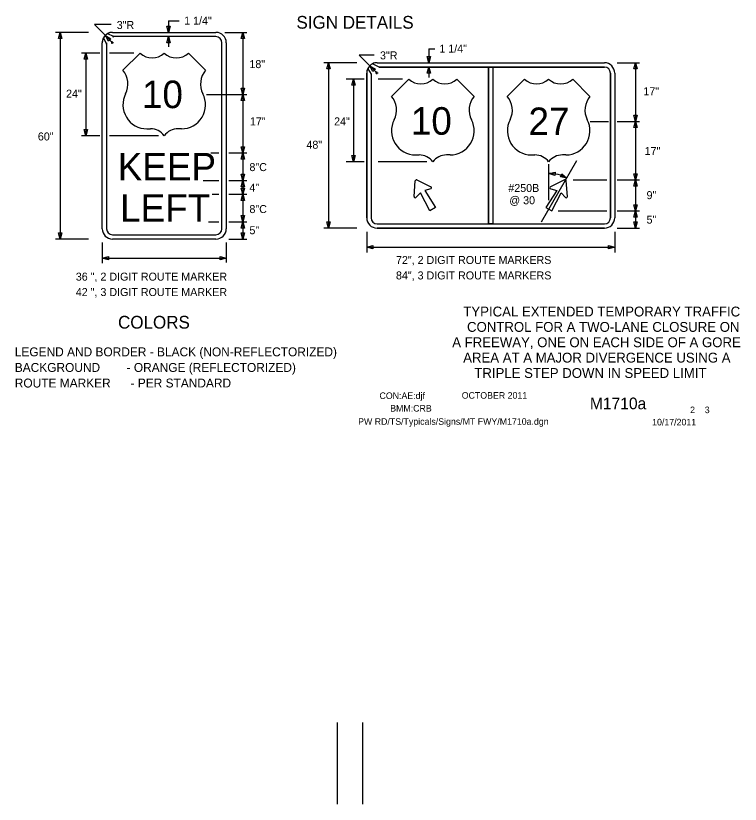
# Model space of a CAD drawing. Extents: x 16630 to 19509, y 5576 to 6998.
# Drawn here: x 17777 to 18460, y 5576 to 6320 of the extents above; entities that cross this region are included whole.
import ezdxf

# ---------------------------------------------------------------- set-up
doc = ezdxf.new("R2010")
doc.units = 0
for name, color, linetype in [('ALI_LEGAL_EX', 7, 'Continuous'), ('BORDER', 7, 'Continuous'), ('BORDER_SIGNAL_WO', 7, 'Continuous'), ('TRAFFIC_SIGNS_PR', 7, 'Continuous'), ('TYPICAL_EX', 7, 'Continuous'), ('TYPICAL_TEXT_DIMEN_PR', 7, 'Continuous')]:
    doc.layers.add(name, color=color, linetype=linetype)

msp = doc.modelspace()

# ---------------------------------------------------------------- linework, layer by layer
at = {"layer": 'ALI_LEGAL_EX'}
for p, q in [((18079.61, 5652.91), (18079.61, 5575.75)), ((18103.61, 5652.91), (18103.61, 5575.75))]:
    msp.add_line(p, q, dxfattribs=at)
at = {"layer": 'TRAFFIC_SIGNS_PR'}
for p, q in [((17860.3, 6300.32), (17859.29, 6298.82)), ((17869.08, 6299.88), (17862.99, 6302.62)), ((17867.88, 6303.94), (17965.38, 6303.94)), ((17858.13, 6118.69), (17858.13, 6294.19)), ((17859.32, 6298.74), (17862.19, 6292.7)), ((17862.19, 6294.19), (17862.19, 6118.69)), ((17965.38, 6299.88), (17867.88, 6299.88)), ((17971.06, 6118.69), (17971.06, 6294.19)), ((17975.13, 6294.19), (17975.13, 6118.69)), ((18119.35, 6271.19), (18113.12, 6274.21)), ((18117.4, 6275.24), (18331.9, 6275.24)), ((18117.4, 6275.24), (18331.9, 6275.24)), ((18119.34, 6271.18), (18222.62, 6271.18)), ((18331.9, 6271.18), (18119.34, 6271.18)), ((18222.62, 6271.18), (18222.62, 6123.31)), ((18226.68, 6271.18), (18226.68, 6123.31)), ((18226.68, 6271.18), (18331.9, 6271.18)), ((18107.65, 6265.49), (18107.65, 6128.99)), ((18107.65, 6128.99), (18107.65, 6265.49)), ((18108.57, 6269.5), (18111.71, 6264.46)), ((18111.71, 6264.44), (18111.71, 6128.99)), ((18111.71, 6264.44), (18111.71, 6128.99)), ((18337.59, 6265.49), (18337.59, 6219.74)), ((18337.59, 6128.99), (18337.59, 6265.49)), ((18341.65, 6265.49), (18341.65, 6128.99)), ((18341.65, 6265.49), (18341.65, 6128.99)), ((18337.59, 6219.74), (18337.59, 6128.99)), ((18152.25, 6149.1), (18153.4, 6163.82)), ((18154.91, 6164.69), (18168.23, 6158.33)), ((18294.38, 6164.69), (18281.07, 6158.33)), ((18297.05, 6149.1), (18295.9, 6163.82)), ((18117.4, 6123.31), (18331.9, 6123.31)), ((18117.4, 6119.24), (18331.9, 6119.24)), ((18331.9, 6119.24), (18117.4, 6119.24)), ((17867.88, 6113), (17965.38, 6113)), ((17965.38, 6108.94), (17867.88, 6108.94))]:
    msp.add_line(p, q, dxfattribs=at)
for points in [[(18119.34, 6271.18), (18119.32, 6271.19)], [(18111.71, 6264.46), (18111.71, 6264.44)], [(18168.07, 6156.36), (18162.34, 6154.78), (18172.56, 6138.61), (18167.16, 6135.49), (18158.27, 6152.43), (18154.04, 6148.26)], [(18281.23, 6156.36), (18286.96, 6154.78), (18276.74, 6138.61), (18282.14, 6135.49), (18291.03, 6152.43), (18295.26, 6148.26)]]:
    msp.add_lwpolyline(points, dxfattribs=at)
msp.add_lwpolyline([(18222.62, 6271.18), (18226.68, 6271.18), (18226.68, 6123.31), (18222.62, 6123.31)], close=True, dxfattribs=at)
for centre, radius, start, end in [((17867.88, 6294.19), 9.75, 90, 180), ((17867.29, 6296.37), 7.6, 85.58319, 124.53531), ((17965.38, 6294.19), 9.75, 0, 90), ((17865.16, 6294.78), 7.06, 145.86811, 184.82317), ((17856.73, 6293.45), 5.51, 352.24294, 7.75653), ((17868.48, 6304.31), 4.47, 262.2432, 277.7568), ((17965.38, 6294.19), 5.69, 0, 90), ((18117.4, 6265.49), 9.75, 90, 180), ((18117.4, 6265.49), 9.75, 90, 180), ((18116.72, 6268.68), 6.6, 84.11162, 123.06374), ((18118.34, 6278.36), 7.24, 277.81035, 278.05403), ((18331.9, 6265.49), 9.75, 0, 90), ((18331.9, 6265.49), 9.75, 0, 90), ((18331.9, 6265.49), 5.69, 0, 89.99421), ((18331.9, 6265.49), 5.69, 0, 90), ((18113.78, 6266.2), 6.17, 147.60925, 186.56283), ((18154.46, 6163.73), 1.06, 64.48226, 175.51774), ((18294.84, 6163.73), 1.06, 4.48226, 115.51774), ((18167.77, 6157.38), 1.06, 285.9885, 64.48226), ((18281.53, 6157.38), 1.06, 115.51774, 254.0115), ((18153.31, 6149.02), 1.06, 175.51775, 314.01151), ((18295.99, 6149.02), 1.06, 225.98849, 4.48225), ((18117.4, 6128.99), 9.75, 180, 270), ((18117.4, 6128.99), 9.75, 180, 270), ((18117.4, 6128.99), 5.69, 180, 270), ((18117.4, 6128.99), 5.69, 180, 270), ((18331.9, 6128.99), 9.75, 270, 0), ((18331.9, 6128.99), 5.69, 270, 0), ((18331.9, 6128.99), 9.75, 270, 0), ((18331.9, 6128.99), 5.69, 270, 0), ((17867.88, 6118.69), 9.75, 180, 270), ((17867.88, 6118.69), 5.69, 180, 270), ((17965.38, 6118.69), 5.69, 270, 0), ((17965.38, 6118.69), 9.75, 270, 0)]:
    msp.add_arc(centre, radius, start, end, dxfattribs=at)
at = {"layer": 'TYPICAL_EX'}
for p, q in [((17877.63, 6268.19), (17893.88, 6284.44)), ((17955.63, 6268.19), (17939.38, 6284.44)), ((18131.01, 6243.58), (18147.26, 6259.83)), ((18209.01, 6243.58), (18192.76, 6259.83)), ((18240.29, 6243.58), (18256.54, 6259.83)), ((18318.29, 6243.58), (18302.04, 6259.83)), ((17900.35, 6212.9), (17903.6, 6212.9)), ((17932.9, 6212.9), (17929.65, 6212.9)), ((18153.74, 6188.29), (18156.99, 6188.29)), ((18186.28, 6188.29), (18183.03, 6188.29)), ((18263.01, 6188.29), (18266.26, 6188.29)), ((18295.56, 6188.29), (18292.31, 6188.29))]:
    msp.add_line(p, q, dxfattribs=at)
for centre, radius, start, end in [((17905.25, 6296.28), 16.42, 226.14041, 313.85958), ((17928, 6296.28), 16.42, 226.14042, 313.85959), ((17862.23, 6255.18), 20.16, 333.09768, 40.19361), ((17971.03, 6255.18), 20.16, 139.80639, 206.90233), ((18158.64, 6271.67), 16.42, 226.14041, 313.85958), ((18181.39, 6271.67), 16.42, 226.14042, 313.85959), ((18267.91, 6271.67), 16.42, 226.14041, 313.85958), ((18290.66, 6271.67), 16.42, 226.14042, 313.85959), ((17900.4, 6235.63), 22.73, 152.6698, 269.90132), ((17932.86, 6235.63), 22.73, 270.09868, 27.3302), ((18115.61, 6230.57), 20.16, 333.09768, 40.19361), ((18224.41, 6230.57), 20.16, 139.80639, 206.90233), ((18224.89, 6230.57), 20.16, 333.09768, 40.19361), ((18333.69, 6230.57), 20.16, 139.80639, 206.90233), ((18153.78, 6211.02), 22.73, 152.6698, 269.90132), ((18186.24, 6211.02), 22.73, 270.09868, 27.3302), ((18263.06, 6211.02), 22.73, 152.6698, 269.90132), ((18295.52, 6211.02), 22.73, 270.09868, 27.3302), ((17903.65, 6196.62), 16.28, 37.1038, 90.13853), ((17929.61, 6196.62), 16.28, 89.86147, 142.8962), ((18157.03, 6172.01), 16.28, 37.1038, 90.13853), ((18182.99, 6172.01), 16.28, 89.86147, 142.8962), ((18266.31, 6172.01), 16.28, 37.1038, 90.13853), ((18292.27, 6172.01), 16.28, 89.86147, 142.8962)]:
    msp.add_arc(centre, radius, start, end, dxfattribs=at)
at = {"layer": 'TYPICAL_TEXT_DIMEN_PR'}
for p, q in [((17866.5, 6311.23), (17850.84, 6311.23)), ((17850.84, 6311.23), (17861.08, 6300.99)), ((17920.6, 6303.94), (17919.03, 6309.8)), ((17919.03, 6309.8), (17920.6, 6309.8)), ((17920.6, 6314.7), (17920.6, 6303.94)), ((17920.6, 6314.7), (17930.71, 6314.7)), ((17920.6, 6309.8), (17922.17, 6309.8)), ((17922.17, 6309.8), (17920.6, 6303.94)), ((17845.3, 6303.94), (17814, 6303.94)), ((17816.77, 6298.08), (17818.34, 6303.94)), ((17818.34, 6303.94), (17818.34, 6108.94)), ((17818.34, 6303.94), (17819.91, 6298.08)), ((17861.08, 6300.99), (17867.64, 6294.43)), ((17864.11, 6295.73), (17861.08, 6300.99)), ((17861.08, 6300.99), (17866.33, 6297.95)), ((17973.67, 6303.94), (17994.63, 6303.94)), ((17989.16, 6298.08), (17990.73, 6303.94)), ((17990.73, 6303.94), (17990.73, 6245.44)), ((17990.73, 6303.94), (17992.3, 6298.08)), ((17818.34, 6298.08), (17816.77, 6298.08)), ((17819.91, 6298.08), (17818.34, 6298.08)), ((17865.22, 6296.84), (17864.11, 6295.73)), ((17866.33, 6297.95), (17865.22, 6296.84)), ((17866.43, 6294.43), (17868.85, 6294.43)), ((17867.64, 6293.22), (17867.64, 6295.64)), ((17919.08, 6294.02), (17920.65, 6299.88)), ((17920.65, 6294.02), (17919.08, 6294.02)), ((17920.65, 6299.88), (17920.65, 6290.13)), ((17920.65, 6299.88), (17922.22, 6294.02)), ((17922.22, 6294.02), (17920.65, 6294.02)), ((17990.73, 6298.08), (17989.16, 6298.08)), ((17992.3, 6298.08), (17990.73, 6298.08)), ((18166.26, 6288.4), (18166.26, 6275.24)), ((18166.26, 6288.4), (18171.78, 6288.4)), ((17855.76, 6284.44), (17838.63, 6284.44)), ((17840.95, 6278.58), (17842.52, 6284.44)), ((17842.52, 6278.58), (17840.95, 6278.58)), ((17842.52, 6284.44), (17842.52, 6206.44)), ((17842.52, 6284.44), (17844.1, 6278.58)), ((17844.1, 6278.58), (17842.52, 6278.58)), ((17887.99, 6284.44), (17865.12, 6284.44)), ((18114.54, 6282.53), (18100.36, 6282.53)), ((18100.36, 6282.53), (18110.51, 6272.38)), ((18166.26, 6275.24), (18164.69, 6281.11)), ((18164.69, 6281.11), (18166.26, 6281.11)), ((18166.26, 6281.11), (18167.83, 6281.11)), ((18167.83, 6281.11), (18166.26, 6275.24)), ((18098.42, 6275.24), (18067.12, 6275.24)), ((18069.89, 6269.38), (18071.46, 6275.24)), ((18071.46, 6275.24), (18071.46, 6119.24)), ((18071.46, 6275.24), (18073.03, 6269.38)), ((18110.51, 6272.38), (18117.16, 6265.73)), ((18113.55, 6267.12), (18110.51, 6272.38)), ((18110.51, 6272.38), (18115.77, 6269.35)), ((18164.74, 6265.32), (18166.31, 6271.18)), ((18164.74, 6265.32), (18166.31, 6271.18)), ((18166.31, 6271.18), (18166.31, 6261.43)), ((18166.31, 6271.18), (18167.88, 6265.32)), ((18166.31, 6271.18), (18167.88, 6265.32)), ((18344.02, 6275.24), (18364.98, 6275.24)), ((18359.51, 6269.38), (18361.08, 6275.24)), ((18361.08, 6275.24), (18361.08, 6219.99)), ((18361.08, 6275.24), (18362.66, 6269.38)), ((18071.46, 6269.38), (18069.89, 6269.38)), ((18073.03, 6269.38), (18071.46, 6269.38)), ((18114.66, 6268.23), (18113.55, 6267.12)), ((18115.77, 6269.35), (18114.66, 6268.23)), ((18115.95, 6265.73), (18118.37, 6265.73)), ((18117.16, 6264.53), (18117.16, 6266.94)), ((18166.31, 6265.32), (18164.74, 6265.32)), ((18166.31, 6265.32), (18164.74, 6265.32)), ((18167.88, 6265.32), (18166.31, 6265.32)), ((18167.88, 6265.32), (18166.31, 6265.32)), ((18361.08, 6269.38), (18359.51, 6269.38)), ((18362.66, 6269.38), (18361.08, 6269.38)), ((18105.28, 6259.83), (18088.15, 6259.83)), ((18093.45, 6253.97), (18095.02, 6259.83)), ((18095.02, 6259.83), (18095.02, 6181.83)), ((18095.02, 6259.83), (18096.59, 6253.97)), ((18141.38, 6259.83), (18118.5, 6259.83)), ((17990.73, 6245.44), (17989.16, 6251.3)), ((17989.16, 6251.3), (17990.73, 6251.3)), ((17990.73, 6251.3), (17992.3, 6251.3)), ((17992.3, 6251.3), (17990.73, 6245.44)), ((18095.02, 6253.97), (18093.45, 6253.97)), ((18096.59, 6253.97), (18095.02, 6253.97)), ((17956.52, 6245.44), (17994.63, 6245.44)), ((17989.16, 6239.58), (17990.73, 6245.44)), ((17990.73, 6245.44), (17990.73, 6190.19)), ((17990.73, 6245.44), (17992.3, 6239.58)), ((17990.73, 6239.58), (17989.16, 6239.58)), ((17992.3, 6239.58), (17990.73, 6239.58)), ((18318.46, 6219.99), (18335.62, 6219.99)), ((18344.02, 6219.99), (18364.98, 6219.99)), ((18361.08, 6219.99), (18359.51, 6225.86)), ((18359.51, 6225.86), (18361.08, 6225.86)), ((18359.51, 6214.13), (18361.08, 6219.99)), ((18361.08, 6225.86), (18362.66, 6225.86)), ((18362.66, 6225.86), (18361.08, 6219.99)), ((18361.08, 6219.99), (18361.08, 6164.74)), ((18361.08, 6219.99), (18362.66, 6214.13)), ((17842.52, 6206.44), (17840.95, 6212.3)), ((17840.95, 6212.3), (17842.52, 6212.3)), ((17842.52, 6212.3), (17844.1, 6212.3)), ((17844.1, 6212.3), (17842.52, 6206.44)), ((18361.08, 6214.13), (18359.51, 6214.13)), ((18362.66, 6214.13), (18361.08, 6214.13)), ((17855.76, 6206.44), (17838.63, 6206.44)), ((17911.12, 6206.44), (17865.12, 6206.44)), ((17960.46, 6190.19), (17968.14, 6190.19)), ((17977.5, 6190.19), (17994.63, 6190.19)), ((17990.73, 6190.19), (17989.16, 6196.05)), ((17989.16, 6196.05), (17990.73, 6196.05)), ((17989.16, 6184.33), (17990.73, 6190.19)), ((17990.73, 6196.05), (17992.3, 6196.05)), ((17992.3, 6196.05), (17990.73, 6190.19)), ((17990.73, 6190.19), (17990.73, 6164.19)), ((17990.73, 6190.19), (17992.3, 6184.33)), ((17990.73, 6184.33), (17989.16, 6184.33)), ((17992.3, 6184.33), (17990.73, 6184.33)), ((18105.28, 6181.83), (18088.15, 6181.83)), ((18095.02, 6181.83), (18093.45, 6187.69)), ((18093.45, 6187.69), (18095.02, 6187.69)), ((18095.02, 6187.69), (18096.59, 6187.69)), ((18096.59, 6187.69), (18095.02, 6181.83)), ((18164.5, 6181.83), (18118.5, 6181.83)), ((18272.68, 6125.34), (18305.92, 6182.93)), ((18279.44, 6145.5), (18279.44, 6179.49)), ((17990.73, 6164.19), (17989.16, 6170.05)), ((17989.16, 6170.05), (17990.73, 6170.05)), ((17990.73, 6170.05), (17992.3, 6170.05)), ((17992.3, 6170.05), (17990.73, 6164.19)), ((18279.47, 6170.94), (18285.46, 6171.9)), ((18285.14, 6168.77), (18279.47, 6170.94)), ((18285.3, 6170.33), (18285.14, 6168.77)), ((18285.46, 6171.9), (18285.3, 6170.33)), ((18290.45, 6167.61), (18291.14, 6169.03)), ((18296.42, 6166.48), (18290.45, 6167.61)), ((18291.14, 6169.03), (18291.82, 6170.44)), ((18291.82, 6170.44), (18296.42, 6166.48)), ((18361.08, 6164.74), (18359.51, 6170.61)), ((18359.51, 6170.61), (18361.08, 6170.61)), ((18361.08, 6170.61), (18362.66, 6170.61)), ((18362.66, 6170.61), (18361.08, 6164.74)), ((17953.44, 6164.19), (17968.14, 6164.19)), ((17977.5, 6164.19), (17994.63, 6164.19)), ((17989.16, 6158.33), (17990.73, 6164.19)), ((17990.73, 6164.19), (17990.73, 6151.19)), ((17990.73, 6164.19), (17992.3, 6158.33)), ((18302.39, 6164.74), (18334.26, 6164.74)), ((18344.02, 6164.74), (18364.98, 6164.74)), ((18359.51, 6158.88), (18361.08, 6164.74)), ((18361.08, 6164.74), (18361.08, 6135.49)), ((18361.08, 6164.74), (18362.66, 6158.88)), ((17990.73, 6158.33), (17989.16, 6158.33)), ((17990.73, 6151.19), (17989.16, 6157.05)), ((17989.16, 6157.05), (17990.73, 6157.05)), ((17992.3, 6158.33), (17990.73, 6158.33)), ((17990.73, 6157.05), (17992.3, 6157.05)), ((17992.3, 6157.05), (17990.73, 6151.19)), ((18361.08, 6158.88), (18359.51, 6158.88)), ((18362.66, 6158.88), (18361.08, 6158.88)), ((17961.79, 6151.19), (17968.14, 6151.19)), ((17977.5, 6151.19), (17994.63, 6151.19)), ((17989.16, 6145.33), (17990.73, 6151.19)), ((17990.73, 6145.33), (17989.16, 6145.33)), ((17990.73, 6151.19), (17990.73, 6125.19)), ((17990.73, 6151.19), (17992.3, 6145.33)), ((17992.3, 6145.33), (17990.73, 6145.33)), ((18361.08, 6135.49), (18359.51, 6141.36)), ((18359.51, 6141.36), (18361.08, 6141.36)), ((18361.08, 6141.36), (18362.66, 6141.36)), ((18362.66, 6141.36), (18361.08, 6135.49)), ((17990.73, 6125.19), (17989.16, 6131.05)), ((17989.16, 6131.05), (17990.73, 6131.05)), ((17990.73, 6131.05), (17992.3, 6131.05)), ((17992.3, 6131.05), (17990.73, 6125.19)), ((18288.26, 6135.49), (18334.26, 6135.49)), ((18344.02, 6135.49), (18364.98, 6135.49)), ((18359.51, 6129.63), (18361.08, 6135.49)), ((18361.08, 6129.63), (18359.51, 6129.63)), ((18361.08, 6135.49), (18361.08, 6119.24)), ((18361.08, 6135.49), (18362.66, 6129.63)), ((18362.66, 6129.63), (18361.08, 6129.63)), ((17958.29, 6125.19), (17968.14, 6125.19)), ((17977.5, 6125.19), (17994.63, 6125.19)), ((17989.16, 6119.33), (17990.73, 6125.19)), ((17990.73, 6125.19), (17990.73, 6108.94)), ((17990.73, 6125.19), (17992.3, 6119.33)), ((18071.46, 6119.24), (18069.89, 6125.11)), ((18069.89, 6125.11), (18071.46, 6125.11)), ((18071.46, 6125.11), (18073.03, 6125.11)), ((18073.03, 6125.11), (18071.46, 6119.24)), ((18361.08, 6119.24), (18359.51, 6125.11)), ((18359.51, 6125.11), (18361.08, 6125.11)), ((18361.08, 6125.11), (18362.66, 6125.11)), ((18362.66, 6125.11), (18361.08, 6119.24)), ((17818.34, 6108.94), (17816.77, 6114.8)), ((17816.77, 6114.8), (17818.34, 6114.8)), ((17818.34, 6114.8), (17819.91, 6114.8)), ((17819.91, 6114.8), (17818.34, 6108.94)), ((17990.73, 6119.33), (17989.16, 6119.33)), ((17990.73, 6108.94), (17989.16, 6114.8)), ((17989.16, 6114.8), (17990.73, 6114.8)), ((17992.3, 6119.33), (17990.73, 6119.33)), ((17990.73, 6114.8), (17992.3, 6114.8)), ((17992.3, 6114.8), (17990.73, 6108.94)), ((18098.42, 6119.24), (18067.12, 6119.24)), ((18107.65, 6115.9), (18107.65, 6096.34)), ((18341.65, 6115.9), (18341.65, 6096.34)), ((18344.02, 6119.24), (18361.15, 6119.24)), ((18344.02, 6119.24), (18364.98, 6119.24)), ((18344.02, 6119.24), (18361.15, 6119.24)), ((17845.3, 6108.94), (17814, 6108.94)), ((17977.5, 6108.94), (17994.63, 6108.94)), ((17858.13, 6105.6), (17858.13, 6086.24)), ((17975.13, 6105.6), (17975.13, 6086.7)), ((18107.65, 6101.27), (18113.51, 6102.84)), ((18107.65, 6101.27), (18341.65, 6101.27)), ((18113.51, 6099.7), (18107.65, 6101.27)), ((18113.51, 6102.84), (18113.51, 6101.27)), ((18113.51, 6101.27), (18113.51, 6099.7)), ((18335.79, 6101.27), (18335.79, 6102.84)), ((18335.79, 6102.84), (18341.65, 6101.27)), ((18341.65, 6101.27), (18335.79, 6099.7)), ((18335.79, 6099.7), (18335.79, 6101.27)), ((17858.13, 6090.97), (17863.99, 6092.54)), ((17863.99, 6092.54), (17863.99, 6090.97)), ((17969.27, 6090.97), (17969.27, 6092.54)), ((17969.27, 6092.54), (17975.13, 6090.97)), ((17858.13, 6090.97), (17975.13, 6090.97)), ((17863.99, 6089.4), (17858.13, 6090.97)), ((17863.99, 6090.97), (17863.99, 6089.4)), ((17975.13, 6090.97), (17969.27, 6089.4)), ((17969.27, 6089.4), (17969.27, 6090.97))]:
    msp.add_line(p, q, dxfattribs=at)
msp.add_arc((18279.63, 6136.5), 34.39, 60.74521, 90.32117, dxfattribs=at)

# ---------------------------------------------------------------- texts
at = {"layer": 'BORDER'}
for s, p in [('TYPICAL EXTENDED TEMPORARY TRAFFIC', (18198.79, 6035.9)), ('CONTROL FOR A TWO-LANE CLOSURE ON', (18202.28, 6021.41)), ('A FREEWAY, ONE ON EACH SIDE OF A GORE', (18188.3, 6006.92)), ('AREA AT A MAJOR DIVERGENCE USING A', (18198.66, 5992.42)), ('TRIPLE STEP DOWN IN SPEED LIMIT', (18209.16, 5977.93))]:
    msp.add_text(s, height=9.3, dxfattribs=at).set_placement(p)
at = {"layer": 'BORDER_SIGNAL_WO'}
for s, height, p in [('CON:AE:djf  ', 6.2, (18119.69, 5958.06)), ('    OCTOBER 2011', 6.2, (18188.08, 5958.34)), ('    M1710a   ', 11, (18301.86, 5948.38)), ('BMM:CRB', 6.2, (18129.81, 5946.17)), (' 2    3 ', 6.2, (18410.45, 5944.7)), ('PW RD/TS/Typicals/Signs/MT FWY/M1710a.dgn      ', 6.2, (18099.55, 5933.71)), ('10/17/2011', 6.2, (18376.93, 5933.13))]:
    msp.add_text(s, height=height, dxfattribs=at).set_placement(p)
at = {"layer": 'TRAFFIC_SIGNS_PR'}
for s, p in [('10', (17895.6, 6232.44)), ('10', (18149.25, 6207.37)), ('27', (18260.26, 6207.01)), ('KEEP', (17872.73, 6164.19)), ('LEFT', (17874.97, 6125.19))]:
    msp.add_text(s, height=26, dxfattribs=at).set_placement(p)
at = {"layer": 'TYPICAL_TEXT_DIMEN_PR'}
for s, height, p in [('1 1/4"', 7.55, (17935.4, 6311.2)), ('SIGN DETAILS', 12, (18041.35, 6307.41)), ('3"R', 7.55, (17871.77, 6307.1)), ('3"R', 7.55, (18120.18, 6278.45)), ('1 1/4"', 7.55, (18176.18, 6284.82)), ('18"', 7.55, (17996.97, 6270.21)), ('24"', 7.55, (17823.97, 6242.33)), ('17"', 7.55, (18368.66, 6244.6)), ('17"', 7.55, (17997.43, 6216.16)), ('24"', 7.55, (18076.88, 6216.16)), ('60"', 7.55, (17797.37, 6201.96)), ('48"', 7.55, (18050.76, 6194.14)), ('17"', 7.55, (18369.86, 6188.24)), ('8"C', 7.55, (17997, 6173.05)), ('4" ', 7.55, (17997, 6153.79)), ('#250B', 7.55, (18241.21, 6153.34)), ('9"', 7.55, (18371.64, 6146.59)), ('@ 30', 7.55, (18242.15, 6141.78)), ('8"C', 7.55, (17997, 6133.46)), ('5"', 7.55, (18371.64, 6123.49)), ('5" ', 7.55, (17997, 6113.49)), ('72", 2 DIGIT ROUTE MARKERS', 7.55, (18135.23, 6085.41)), ('36 ", 2 DIGIT ROUTE MARKER', 7.55, (17833.18, 6069.71)), ('84", 3 DIGIT ROUTE MARKERS', 7.55, (18135.23, 6070.86)), ('42 ", 3 DIGIT ROUTE MARKER', 7.55, (17833.18, 6055.16)), ('COLORS', 12, (17873, 6024.47)), ('LEGEND AND BORDER - BLACK (NON-REFLECTORIZED)', 8.4, (17775.62, 5998.31)), ('BACKGROUND        - ORANGE (REFLECTORIZED)', 8.4, (17775.62, 5983.61)), ('ROUTE MARKER      - PER STANDARD', 8.4, (17775.62, 5968.91))]:
    msp.add_text(s, height=height, dxfattribs=at).set_placement(p)

doc.saveas('drawing.dxf')
